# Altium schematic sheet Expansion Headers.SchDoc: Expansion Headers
size A3; CompanyName: Hitex GmbH; Address1: Greschbachstr. 12; Address2: 76229 Karlsruhe, Germany; Address3: www.hitex.com; DocumentNumber: 8; SheetNumber: 8; SheetTotal: 8; PageSetup: Record=PageOptions¦CenterHorizontal=True¦CenterVertical=True¦PrintScale=1.04¦XCorrection=1.00¦YCorrection=1.00¦PrintKind=0¦BorderSize=5000000¦LeftOffset=0¦BottomOffset=0¦Orientation=2¦PaperLength=1000¦PaperWidth=1000¦Scale=100¦PaperSource=7¦PrintQuality=1200¦MediaType=1¦DitherType=10¦PaperKind=A3¦PrintScaleMode=1
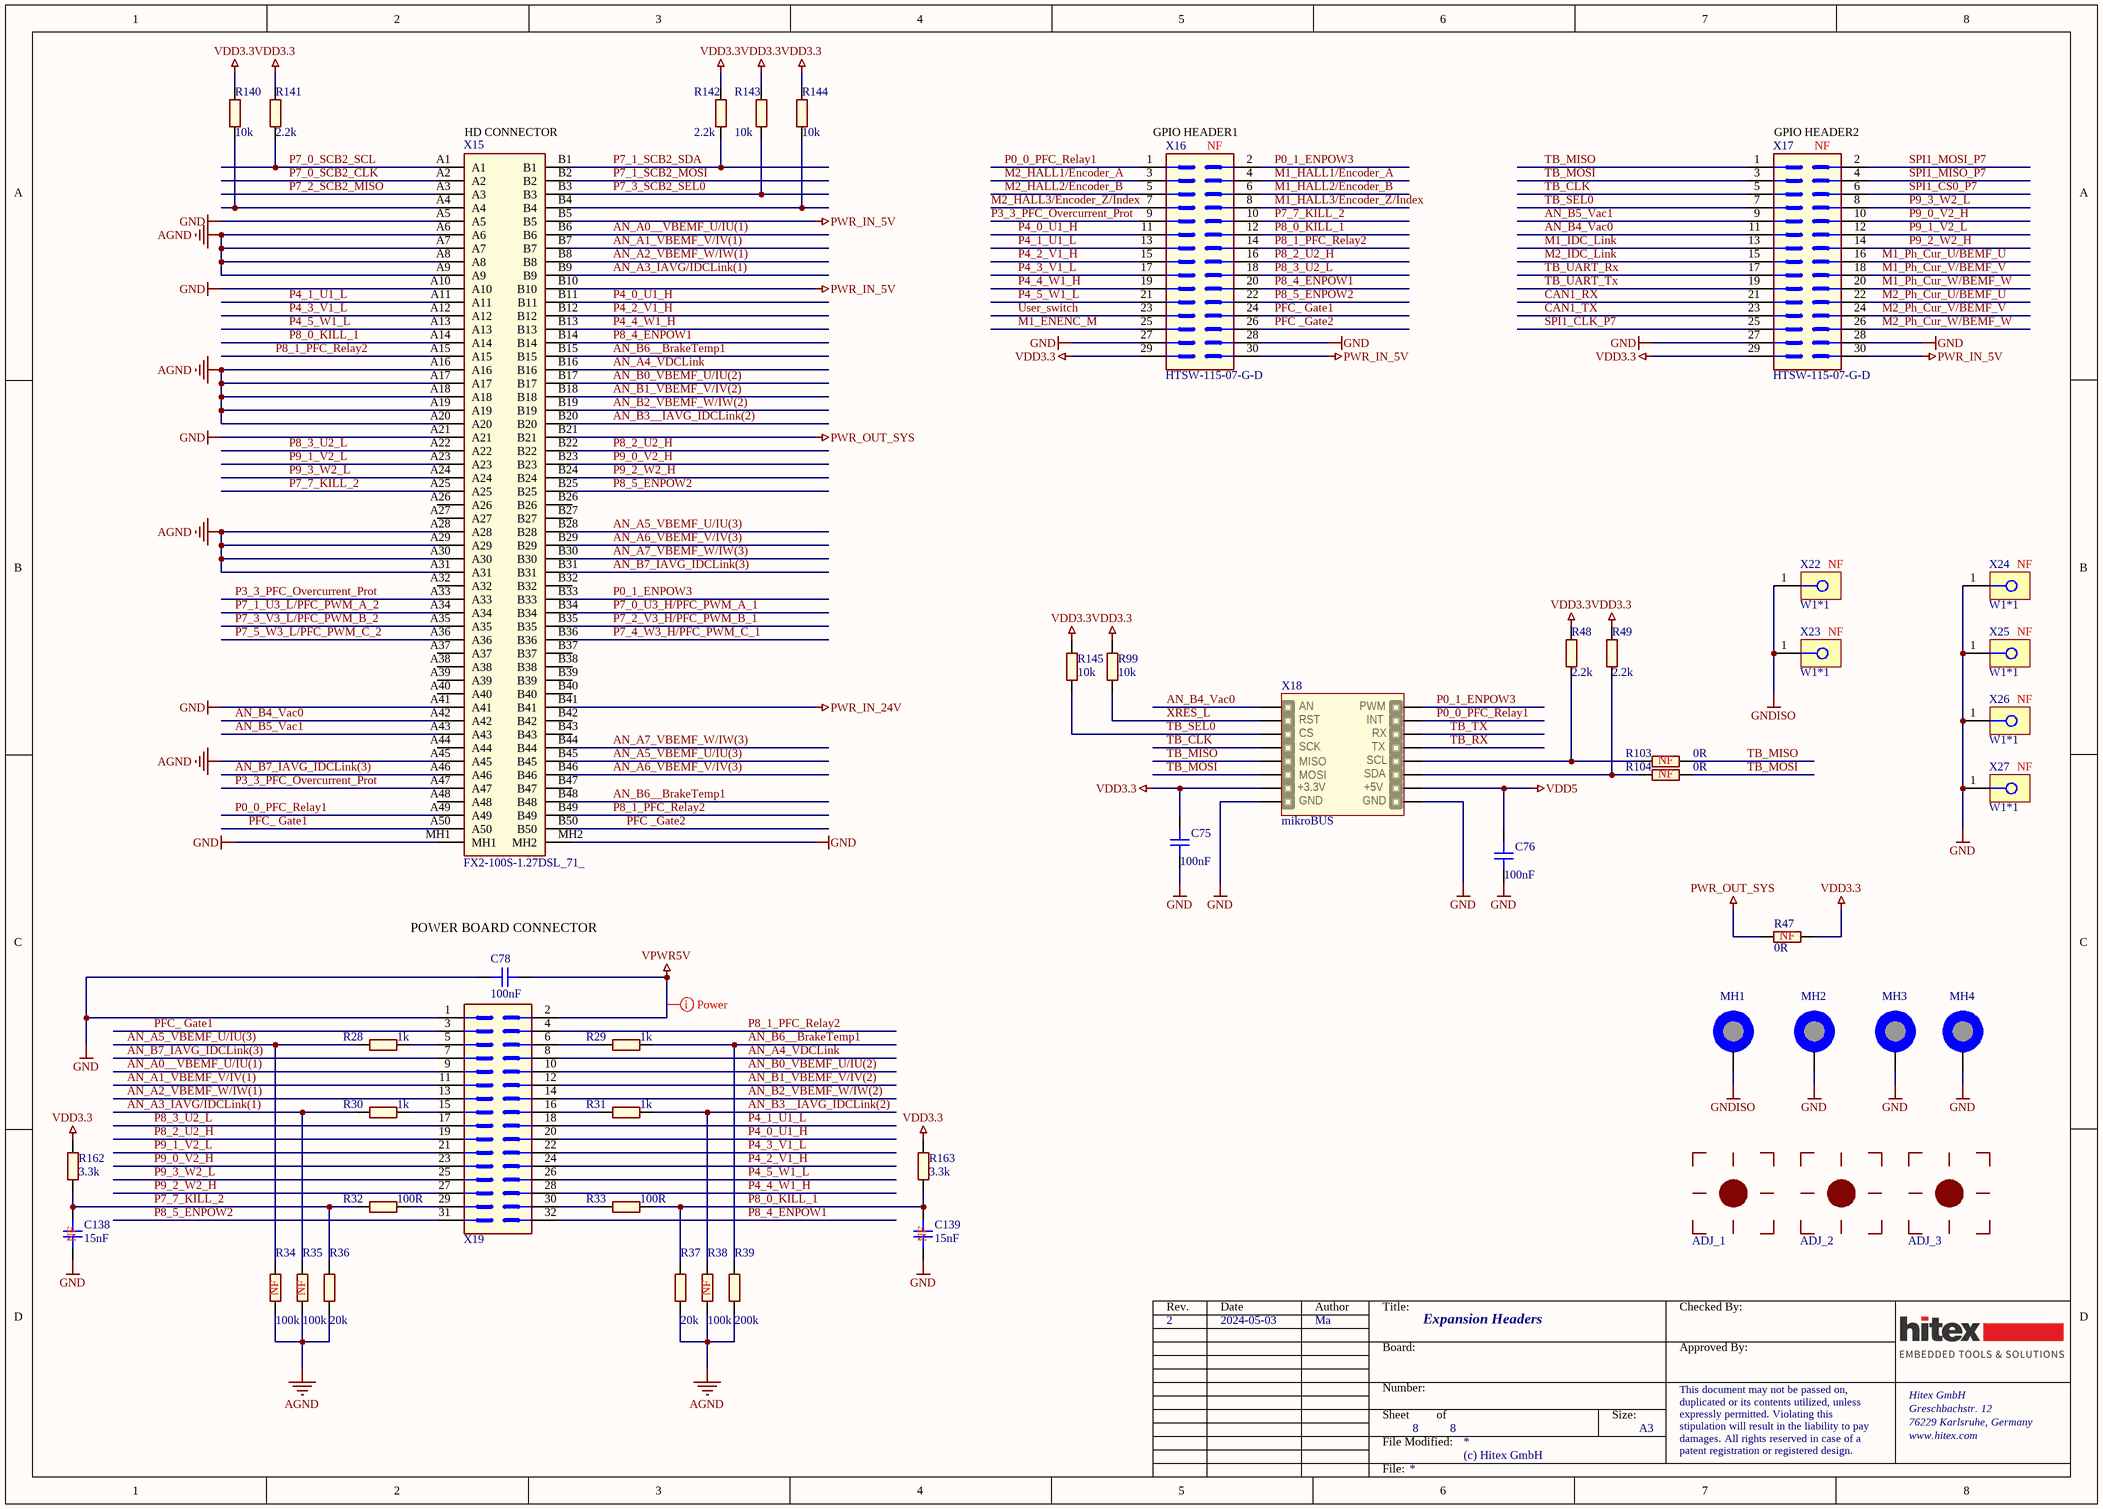
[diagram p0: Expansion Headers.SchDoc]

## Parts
ADJ_1  Fiducial Round 1.5mm  [FIDUCIAL_ROUND_1.5MM]  (value not drawn)  (no BOM)
ADJ_2  Fiducial Round 1.5mm  [FIDUCIAL_ROUND_1.5MM]  (value not drawn)  (no BOM)
ADJ_3  Fiducial Round 1.5mm  [FIDUCIAL_ROUND_1.5MM]  (value not drawn)  (no BOM)
C75  100nF  [CAPC1005X60N]
C76  100nF  [CAPC1005X60N]
C78  100nF  [CAPC1005X55N-0]
C138  15nF  [CAPC1005X55N-0]
C139  15nF  [CAPC1005X55N-0]
MH1  Mounting Hole for M3  [MOUNTING-HOLE_M3_L]  (value not drawn)  (no BOM)
MH2  Mounting Hole for M3  [MOUNTING-HOLE_M3_L]  (value not drawn)  (no BOM)
MH3  Mounting Hole for M3  [MOUNTING-HOLE_M3_L]  (value not drawn)  (no BOM)
MH4  Mounting Hole for M3  [MOUNTING-HOLE_M3_L]  (value not drawn)  (no BOM)
R28  1k  [RESC1005X40N]
R29  1k  [RESC1005X40N]
R30  1k  [RESC1005X40N]
R31  1k  [RESC1005X40N]
R32  100R  [RESC1005X40N]
R33  100R  [RESC1005X40N]
R34  100k  [RESC1005X40N]
R35  100k  [RESC1005X40N]
R36  20k  [RESC1005X40N]
R37  20k  [RESC1005X40N]
R38  100k  [RESC1005X40N]
R39  200k  [RESC1005X40N]
R47  0R  [RESC1005X03N]
R48  2.2k  [RESC1005X40N]
R49  2.2k  [RESC1005X40N]
R99  10k  [RESC1005X40N]
R103  0R  [RESC1005X03N]
R104  0R  [RESC1005X03N]
R140  10k  [RESC1005X40N]
R141  2.2k  [RESC1005X40N]
R142  2.2k  [RESC1005X40N]
R143  10k  [RESC1005X40N]
R144  10k  [RESC1005X40N]
R145  10k  [RESC1005X40N]
R162  3.3k  [RESC1005X40N]
R163  3.3k  [RESC1005X40N]
X15  FX2-100S-1.27DSL_71_  [FX2100S127DSL71]
X16  HTSW-115-07-G-D  [HDRV30W64P254_2X15_3810X502X838B]
X17  HTSW-115-07-G-D  [HDRV30W64P254_2X15_3810X502X838B]
X18  mikroBUS  [MIKROBUS HOST CONN.]  (no BOM)
X19  Header 16X2  [HDRV32W64P254_2X16_4070X508X838B]  (value not drawn)
X22  W1*1  [HDR1X1]  (no BOM)
X23  W1*1  [HDR1X1]  (no BOM)
X24  W1*1  [HDR1X1]  (no BOM)
X25  W1*1  [HDR1X1]  (no BOM)
X26  W1*1  [HDR1X1]  (no BOM)
X27  W1*1  [HDR1X1]  (no BOM)

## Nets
AGND: R34.1 R35.1 R36.1 R37.1 R38.1 R39.1 X15.A6 X15.A7 X15.A8 X15.A9 X15.A16 X15.A17 X15.A18 X15.A19 X15.A20 X15.A28 X15.A29 X15.A30 X15.A31 X15.A45
GND: C75.1 C76.1 C78.2 C138.2 C139.2 MH2.1 MH3.1 MH4.1 X15.A5 X15.A10 X15.A21 X15.A41 X15.MH1 X15.MH2 X16.27 X16.28 X17.27 X17.28 X18.8(GND) X18.9(GND) X19.1 X24.1 X25.1 X26.1 X27.1
GNDISO: MH1.1 X22.1 X23.1
PWR_IN_5V: X15.B5 X15.B10 X16.30 X17.30
PWR_IN_24V: X15.B41
PWR_OUT_SYS: R47.1 X15.B21
VDD3.3: C75.2 R47.2 R48.2 R49.2 R99.2 R140.2 R141.2 R142.2 R143.2 R144.2 R145.2 R162.2 R163.2 X16.29 X17.29 X18.7(3.3V)
VDD5: C76.2 X18.10(5V)
VPWR5V: C78.1 X19.2
AN_A0__VBEMF_U/IU(1): X15.B6 X19.9
AN_A1_VBEMF_V/IV(1): X15.B7 X19.11
AN_A2_VBEMF_W/IW(1): X15.B8 X19.13
AN_A3_IAVG/IDCLink(1): R30.1 R35.2 X15.B9
AN_A4_VDCLink: X15.B16 X19.8
AN_A5_VBEMF_U/IU(3): R28.1 R34.2 X15.B28 X15.B45
AN_A6_VBEMF_V/IV(3): X15.B29 X15.B46
AN_A7_VBEMF_W/IW(3): X15.B30 X15.B44
AN_B0_VBEMF_U/IU(2): X15.B17 X19.10
AN_B1_VBEMF_V/IV(2): X15.B18 X19.12
AN_B2_VBEMF_W/IW(2): X15.B19 X19.14
AN_B3__IAVG_IDCLink(2): R31.2 R38.2 X15.B20
AN_B4_Vac0: X15.A42 X17.11 X18.1(AN)
AN_B5_Vac1: X15.A43 X17.9
AN_B6__BrakeTemp1: R29.2 R39.2 X15.B15 X15.B48
AN_B7_IAVG_IDCLink(3): X15.A46 X15.B31 X19.7
CAN1_RX: X17.21
CAN1_TX: X17.23
M1_ENENC_M: X16.25
M1_HALL1/Encoder_A: X16.4
M1_HALL2/Encoder_B: X16.6
M1_HALL3/Encoder_Z/Index: X16.8
M1_IDC_Link: X17.13
M1_Ph_Cur_U/BEMF_U: X17.16
M1_Ph_Cur_V/BEMF_V: X17.18
M1_Ph_Cur_W/BEMF_W: X17.20
M2_HALL1/Encoder_A: X16.3
M2_HALL2/Encoder_B: X16.5
M2_HALL3/Encoder_Z/Index: X16.7
M2_IDC_Link: X17.15
M2_Ph_Cur_U/BEMF_U: X17.22
M2_Ph_Cur_V/BEMF_V: X17.24
M2_Ph_Cur_W/BEMF_W: X17.26
P0_0_PFC_Relay1: X15.A49 X16.1 X18.15(INT)
P0_1_ENPOW3: X15.B33 X16.2 X18.16(PWM)
P3_3_PFC_Overcurrent_Prot: X15.A33 X15.A47 X16.9
P4_0_U1_H: X15.B11 X16.11 X19.20
P4_1_U1_L: X15.A11 X16.13 X19.18
P4_2_V1_H: X15.B12 X16.15 X19.24
P4_3_V1_L: X15.A12 X16.17 X19.22
P4_4_W1_H: X15.B13 X16.19 X19.28
P4_5_W1_L: X15.A13 X16.21 X19.26
P7_0_SCB2_CLK: X15.A2
P7_0_SCB2_SCL: R141.1 X15.A1
P7_0_U3_H/PFC_PWM_A_1: X15.B34
P7_1_SCB2_MOSI: X15.B2
P7_1_SCB2_SDA: R142.1 X15.B1
P7_1_U3_L/PFC_PWM_A_2: X15.A34
P7_2_SCB2_MISO: X15.A3
P7_2_V3_H/PFC_PWM_B_1: X15.B35
P7_3_SCB2_SEL0: R143.1 X15.B3
P7_3_V3_L/PFC_PWM_B_2: X15.A35
P7_4_W3_H/PFC_PWM_C_1: X15.B36
P7_5_W3_L/PFC_PWM_C_2: X15.A36
P7_7_KILL_2: C138.1 R32.1 R36.2 R162.1 X15.A25 X16.10
P8_0_KILL_1: C139.1 R33.2 R37.2 R163.1 X15.A14 X16.12
P8_1_PFC_Relay2: X15.A15 X15.B49 X16.14 X19.4
P8_2_U2_H: X15.B22 X16.16 X19.19
P8_3_U2_L: X15.A22 X16.18 X19.17
P8_4_ENPOW1: X15.B14 X16.20 X19.32
P8_5_ENPOW2: X15.B25 X16.22 X19.31
P9_0_V2_H: X15.B23 X17.10 X19.23
P9_1_V2_L: X15.A23 X17.12 X19.21
P9_2_W2_H: X15.B24 X17.14 X19.27
P9_3_W2_L: X15.A24 X17.8 X19.25
PFC _Gate2: X15.B50 X16.26
PFC_ Gate1: X15.A50 X16.24 X19.3
SPI1_CLK_P7: X17.25
SPI1_CS0_P7: X17.6
SPI1_MISO_P7: X17.4
SPI1_MOSI_P7: X17.2
TB_CLK: X17.5 X18.4(SCK)
TB_MISO: R103.1 X17.1 X18.5(MISO)
TB_MOSI: R104.1 X17.3 X18.6(MOSI)
TB_RX: X18.13(TX)
TB_SEL0: R145.1 X17.7 X18.3(CS)
TB_TX: X18.14(RX)
TB_UART_Rx: X17.17
TB_UART_Tx: X17.19
User_switch: X16.23
XRES_L: R99.1 X18.2(RST)
NetR28_2: R28.2 X19.5
NetR29_1: R29.1 X19.6
NetR30_2: R30.2 X19.15
NetR31_1: R31.1 X19.16
NetR32_2: R32.2 X19.29
NetR33_1: R33.1 X19.30
NetR48_1: R48.1 R103.2 X18.12(SCL)
NetR49_1: R49.1 R104.2 X18.11(SDA)
NetR140_1: R140.1 X15.A4
NetR144_1: R144.1 X15.B4

Not connected (* = marked no-connect by the designer): X15 A26 A27 A32 A37 A38 A39 A40 A44 A48 B26 B27 B32 B37 B38 B39 B40 B42 B43 B47

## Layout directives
net class Power: VPWR5V

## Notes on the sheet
- (near X15) HD CONNECTOR
- (near X16) GPIO HEADER1
- (near X16) NF
- (near X17) GPIO HEADER2
- (near X17) NF
- (near X22) NF
- (near X24) NF
- NF
- (near R103) NF
- (near R104) NF
- (near C78) POWER BOARD CONNECTOR
- (near R47) NF
- (near C138) NF
- (near C139) NF
- (near R34) NF
- (near R35) NF
- (near R38) NF
- 2
- 2024-05-03
- Ma

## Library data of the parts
ADJ_1-ADJ_3 = Fiducial_Round_1.5mm: Fiducial Round 1.5mm Copper, 3mm Soldermask; PartNumber: -NoPartNumber-; Designer: Ma; CheckOrientation: false
C75 C76 = 507459: CAP / CERA / 100nF / 50V / 10% / X7R (EIA) / -55°C to 125°C / 0402(1005) / SMD / -; Multiple Parts: No; Manufacturer: TDK Corporation; Manufacturer Order Number: C1005X7R1H104K050BE; Symbol Type: Capacitor; Single; Standard; 2 Pins; Alternate View: Yes; Article Number: 507459; Version Number: V01; Combined Parameters: TC:X7R (EIA);Tol.:-10%/+10%;Vdc:50V; QuickPick: 100nF / 50V / 10% / X7R (EIA) / 0402 (1005); Type: Standard; Style: Single; Package Metric: 1005; Package Imperial: 0402; ComponentStatus: Released; PLMStatus: Active; HTX: 01.22.0596.0
C78 = 310625: CAP / CERA / 100nF / 50V / 10% / X7R (EIA) / -55°C to 125°C / 0402(1005) / SMD / -; Multiple Parts: No; Legacy PartNumber: CAP01010920; Manufacturer: MuRata; Manufacturer Order Number: GRM155R71H104KE14D; Symbol Type: Capacitor; Single; Standard; 2 Pins; Alternate View: Yes; Article Number: 310625; Version Number: V01; Combined Parameters: TC:X7R (EIA);Tol.:-10%/+10%;Vdc:50V; QuickPick: 100nF / 50V / 10% / X7R (EIA) / 0402 (1005M); Type: Standard; Style: Single; Package Metric: 1005; Package Imperial: 0402; ComponentStatus: Released; PLMStatus: Active; HTX: 01.22.0596.0
C138 C139 = 289336: CAP / CERA / 15nF / 50V / 20% / X7R (EIA) / -55°C to 125°C / 0402(1005) / SMD / -; Multiple Parts: No; Legacy PartNumber: CAP01006940; Manufacturer: MuRata; Manufacturer Order Number: GCM155R71H153MA55; Symbol Type: Capacitor; Single; Standard; 2 Pins; Alternate View: Yes; Article Number: 289336; Version Number: V01; Combined Parameters: TC:X7R (EIA);Tol.:-20%/+20%;Vdc:50V; QuickPick: 15nF / 50V / 20% / X7R (EIA) / 0402 (1005); Type: Standard; Style: Single; Automotive Qualified: AEC Q200; Package Metric: 1005; Package Imperial: 0402; ComponentStatus: Released; PLMStatus: Active; HTX: 01.22.0662.0
MH1-MH4 = Mounting_Hole_M3: PartNumber: -NoPartNumber-; Designer: Ma; CheckOrientation: false
R28-R31 = 341597: RES / STD / 1k / 63mW / 1% / 100ppm/K / -55°C to 155°C / 0402(1005) / SMD / -; Multiple Parts: No; Legacy PartNumber: RES01800343; Manufacturer: Vishay; Manufacturer Order Number: CRCW04021K00FK; Symbol Type: Resistor; Single; Standard; 2 Pins; Alternate View: Yes; Article Number: 341597; Version Number: V01; Combined Parameters: TCR:100ppm/K;Tol.:-1%/+1%;Vdc:50V;Idc:-;P:63mW; QuickPick: 1k / 1% / 0.063 / 0402 (1005); Style: Single; Automotive Qualified: AEC Q200; Package Metric: 1005; Package Imperial: 0402; ComponentStatus: Released; PLMStatus: Active; Voltage DC (max): 50V; HTX: 01.02.0701.0
R32 R33 = 341027: RES / STD / 100R / 63mW / 1% / 100ppm/K / -55°C to 155°C / 0402(1005) / SMD / -; Multiple Parts: No; Legacy PartNumber: RES01800229; Manufacturer: Vishay; Manufacturer Order Number: CRCW0402100RFK; Symbol Type: Resistor; Single; Standard; 2 Pins; Alternate View: Yes; Article Number: 341027; Version Number: V01; Combined Parameters: TCR:100ppm/K;Tol.:-1%/+1%;Vdc:50V;Idc:-;P:63mW; QuickPick: 100R / 1% / 0.063 / 0402 (1005); Style: Single; Automotive Qualified: AEC Q200; Package Metric: 1005; Package Imperial: 0402; ComponentStatus: Released; PLMStatus: Active; Voltage DC (max): 50V; HTX: 01.02.1130.0
R34 R35 R38 = 342737: RES / STD / 100k / 63mW / 1% / 100ppm/K / -55°C to 155°C / 0402(1005) / SMD / -; Multiple Parts: No; Legacy PartNumber: RES01800571; Manufacturer: Vishay; Manufacturer Order Number: CRCW0402100KFK; Symbol Type: Resistor; Single; Standard; 2 Pins; Alternate View: Yes; Article Number: 342737; Version Number: V01; Combined Parameters: TCR:100ppm/K;Tol.:-1%/+1%;Vdc:50V;Idc:-;P:63mW; QuickPick: 100k / 1% / 0.063 / 0402 (1005); Style: Single; Automotive Qualified: AEC Q200; Package Metric: 1005; Package Imperial: 0402; ComponentStatus: Released; PLMStatus: Active; Voltage DC (max): 50V; HTX: 01.02.0716.0
R36 R37 = 342327: RES / STD / 20k / 63mW / 1% / 100ppm/K / -55°C to 155°C / 0402(1005) / SMD / -; Multiple Parts: No; Legacy PartNumber: RES01800489; Manufacturer: Vishay; Manufacturer Order Number: CRCW040220K0FK; Symbol Type: Resistor; Single; Standard; 2 Pins; Alternate View: Yes; Article Number: 342327; Version Number: V01; Combined Parameters: TCR:100ppm/K;Tol.:-1%/+1%;Vdc:50V;Idc:-;P:63mW; QuickPick: 20k / 1% / 0.063 / 0402 (1005); Style: Single; Automotive Qualified: AEC Q200; Package Metric: 1005; Package Imperial: 0402; ComponentStatus: Released; PLMStatus: Active; Voltage DC (max): 50V; HTX: 01.02.1140.0
R39 = 342897: RES / STD / 200k / 63mW / 1% / 100ppm/K / -55°C to 155°C / 0402(1005) / SMD / -; Multiple Parts: No; Legacy PartNumber: RES01800603; Manufacturer: Vishay; Manufacturer Order Number: CRCW0402200KFK; Symbol Type: Resistor; Single; Standard; 2 Pins; Alternate View: Yes; Article Number: 342897; Version Number: V01; Combined Parameters: TCR:100ppm/K;Tol.:-1%/+1%;Vdc:50V;Idc:-;P:63mW; QuickPick: 200k / 1% / 0.063 / 0402 (1005); Style: Single; Automotive Qualified: AEC Q200; Package Metric: 1005; Package Imperial: 0402; ComponentStatus: Released; PLMStatus: Active; Voltage DC (max): 50V; HTX: 01.02.1141.0
R47 R103 R104 = 327372: RES / STD / 0R / 63mW / 0R / 0ppm/K / -55°C to 155°C / 0402(1005) / SMD / -; Multiple Parts: No; Legacy PartNumber: RES00000001; Manufacturer: Yageo; Manufacturer Order Number: RC0402JR-070RL; Symbol Type: Resistor; Single; Standard; 2 Pins; Alternate View: Yes; Article Number: 327372; Version Number: V01; Combined Parameters: TCR:0ppm/K;Tol.:-0R/+0R;Vdc:50V;Idc:1A;P:63mW; QuickPick: 0R / 0R / 0.063 / 0402 (1005); Style: Single; Package Metric: 1005; Package Imperial: 0402; ComponentStatus: Released; PLMStatus: Active; Voltage DC (max): 50V; HTX: 01.02.0902.0
R48 R49 R141 R142 = 341777: RES / STD / 2.2k / 63mW / 1% / 100ppm/K / -55°C to 155°C / 0402(1005) / SMD / -; Multiple Parts: No; Legacy PartNumber: RES01800379; Manufacturer: Vishay; Manufacturer Order Number: CRCW04022K20FK; Symbol Type: Resistor; Single; Standard; 2 Pins; Alternate View: Yes; Article Number: 341777; Version Number: V01; Combined Parameters: TCR:100ppm/K;Tol.:-1%/+1%;Vdc:50V;Idc:-;P:63mW; QuickPick: 2.2k / 1% / 0.063 / 0402 (1005); Style: Single; Automotive Qualified: AEC Q200; Package Metric: 1005; Package Imperial: 0402; ComponentStatus: Released; PLMStatus: Active; Voltage DC (max): 50V; HTX: 01.02.0722.0
R99 R140 R143-R145 = 342167: RES / STD / 10k / 63mW / 1% / 100ppm/K / -55°C to 155°C / 0402(1005) / SMD / -; Multiple Parts: No; Legacy PartNumber: RES01800457; Manufacturer: Vishay; Manufacturer Order Number: CRCW040210K0FK; Symbol Type: Resistor; Single; Standard; 2 Pins; Alternate View: Yes; Article Number: 342167; Version Number: V01; Combined Parameters: TCR:100ppm/K;Tol.:-1%/+1%;Vdc:50V;Idc:-;P:63mW; QuickPick: 10k / 1% / 0.063 / 0402 (1005); Style: Single; Automotive Qualified: AEC Q200; Package Metric: 1005; Package Imperial: 0402; ComponentStatus: Released; PLMStatus: Active; Voltage DC (max): 50V; HTX: 01.02.0703.0
R162 R163 = 341882: RES / STD / 3.3k / 63mW / 1% / 100ppm/K / -55°C to 155°C / 0402(1005) / SMD / -; Multiple Parts: No; Legacy PartNumber: RES01800400; Manufacturer: Vishay; Manufacturer Order Number: CRCW04023K30FK; Symbol Type: Resistor; Single; Standard; 2 Pins; Alternate View: Yes; Article Number: 341882; Version Number: V01; Combined Parameters: TCR:100ppm/K;Tol.:-1%/+1%;Vdc:50V;Idc:-;P:63mW; QuickPick: 3.3k / 1% / 0.063 / 0402 (1005); Style: Single; Automotive Qualified: AEC Q200; Package Metric: 1005; Package Imperial: 0402; ComponentStatus: Released; PLMStatus: Active; Voltage DC (max): 50V; HTX: 01.02.0743.0
X15 = FX2-100S-1.27DSL_71_: Hirose FX2 Series 1.27mm 100 Way 2 Row Right Angle PCB Socket Surface Mount Board to Board; Manufacturer_Part_Number: FX2-100S-1.27DSL(71); Geometry.Height: 7.8mm; HTX: 03.13.0605.0
X16 X17 = 377714: Through-Hole 0.635mm Sq. Double Row Vertical Post Header; Legacy PartNumber: CON01500070; Manufacturer: Samtec; Article Number: 377714; Version Number: V01; Legacy DeviceID: SAM_HTSW-115-07-G-D; Combined Parameters: Board-to-Board Header (male);15x2;Mounting:THT;Orient:0° (vertical);Shielded:No; QuickPick: 0° (vertical) / Board-to-Board; Style: Strip; Automotive Qualified: No; ComponentStatus: Released; PLMStatus: Active; Second Source allowed: Yes; Voltage DC (max): na; HTX: 03.20.0018.0
X18 = mikroBUS_Host: mikroBUS Socket; HTX: 03.13.0455.0
X19 = 378123: Through hole .025 SQ Post Header, 2.54mm pitch, 32 pin, vertical, double row; Legacy PartNumber: CON01500107; Manufacturer: Samtec; Manufacturer Order Number: TSW-116-07-L-D; Article Number: 378123; Version Number: V01; Legacy DeviceID: SAM_TSW-116-07-L-D; Value: TSW-116-07-L-D; Combined Parameters: Board-to-Board Header (male);16x2;Mounting:THT;Orient:0° (vertical);Shielded:No; QuickPick: 0° (vertical) / Board-to-Board; Style: Strip; Automotive Qualified: No; ComponentStatus: Released; PLMStatus: Active; Second Source allowed: Yes; Voltage DC (max): na; HTX: 03.13.0537.0
X22-X27 = W1*1: Wrap-Leiste 1-reihig  1-polig; PartNumber: 03.20.0000.0; Designer: Ma; CheckOrientation: false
